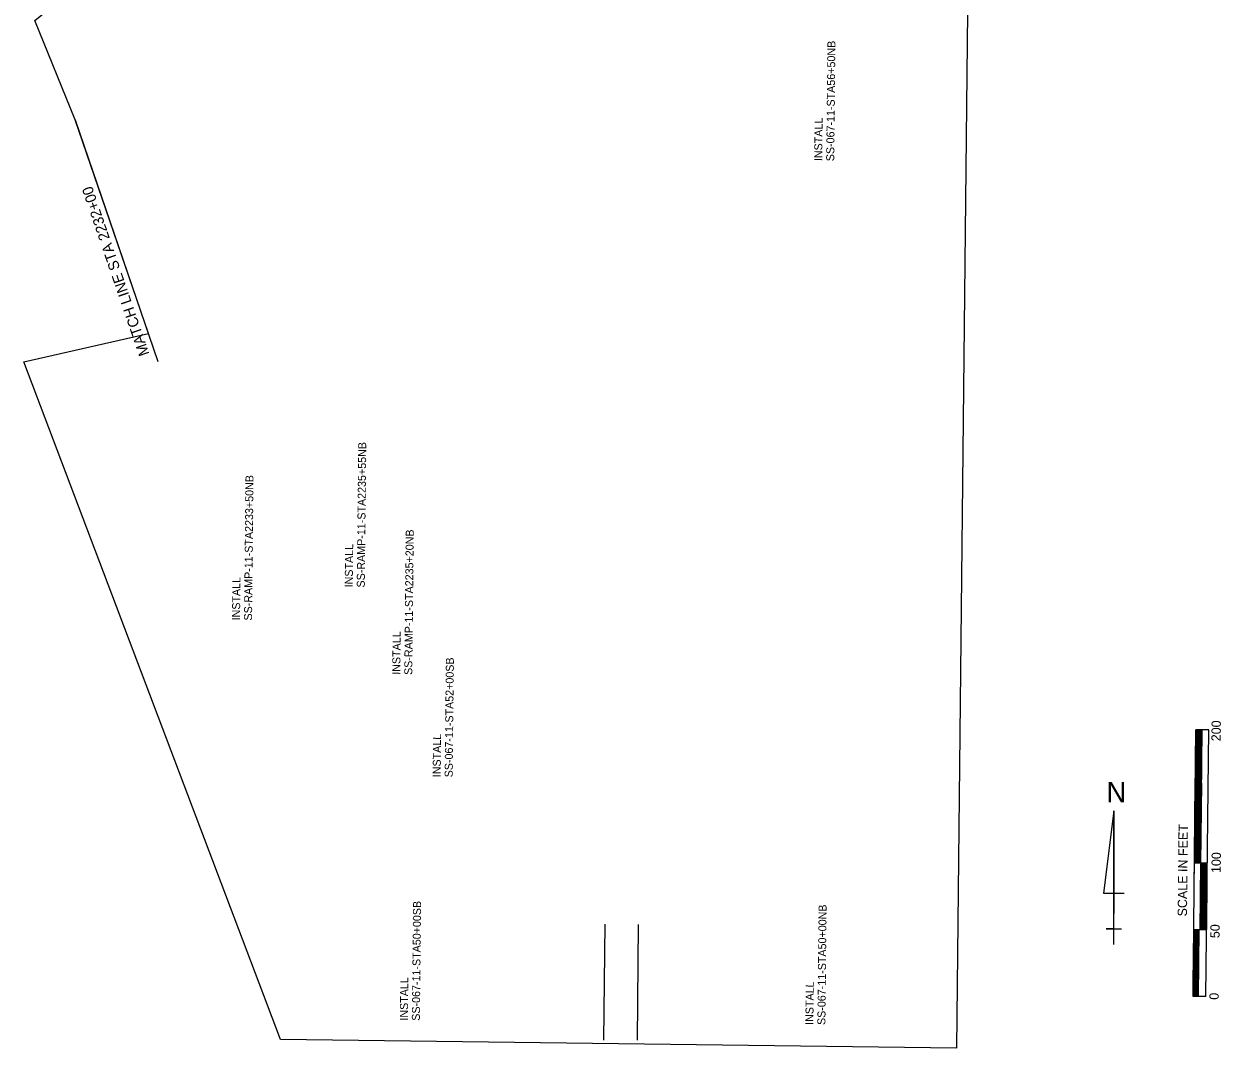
# Model space of a CAD drawing. Extents: x 1727808 to 1728800, y 771204 to 773048.
# Drawn here: x 1727861 to 1728759, y 771204 to 771972 of the extents above; entities that cross this region are included whole.
import ezdxf

# ---------------------------------------------------------------- set-up
doc = ezdxf.new("R2010")
doc.units = 0
for name, color, linetype in [('R_6IN_DBL_YELLOW_THERMOPLASTIC', 7, 'Continuous'), ('R_8IN_SOLID_WHITE_THERMO', 7, 'Continuous'), ('R_8IN_SOLID_YELLOW_THERMO', 7, 'Continuous'), ('R_PM_DOTTED_LINE', 7, 'Continuous'), ('R_RPM_TYPE 2_RED-WHITE', 7, 'Continuous'), ('R_WORDS_WHITE_THERMO', 7, 'Continuous')]:
    doc.layers.add(name, color=color, linetype=linetype)

msp = doc.modelspace()

# ---------------------------------------------------------------- linework, layer by layer
at = {"layer": 'R_6IN_DBL_YELLOW_THERMOPLASTIC'}
for p, q in [((1728296.7, 771296.95), (1728295.79, 771209.93)), ((1728321.73, 771296.68), (1728320.82, 771209.89))]:
    msp.add_line(p, q, dxfattribs=at)
at = {"layer": 'R_8IN_SOLID_WHITE_THERMO'}
msp.add_line((1727899.69, 771899.83), (1727961.67, 771718.73), dxfattribs=at)
at = {"layer": 'R_8IN_SOLID_YELLOW_THERMO'}
for p, q in [((1728738.52, 771322.68), (1728739.78, 771442.68)), ((1728739.53, 771342.68), (1728740.58, 771442.67)), ((1728749.4, 771442.58), (1728739.8, 771442.68)), ((1728740.33, 771342.67), (1728741.38, 771442.66)), ((1728741.13, 771342.66), (1728742.18, 771442.65)), ((1728741.93, 771342.65), (1728742.98, 771442.64)), ((1728742.73, 771342.64), (1728743.78, 771442.64)), ((1728743.53, 771342.63), (1728744.58, 771442.63)), ((1728747.29, 771242.59), (1728749.38, 771442.58)), ((1728737.69, 771242.69), (1728739.36, 771402.68)), ((1728743.53, 771342.63), (1728744.16, 771402.63)), ((1728748.34, 771342.58), (1728738.74, 771342.68)), ((1728743.01, 771292.64), (1728743.54, 771342.63)), ((1728743.81, 771292.63), (1728744.33, 771342.62)), ((1728744.61, 771292.62), (1728745.13, 771342.62)), ((1728745.41, 771292.61), (1728745.93, 771342.61)), ((1728746.21, 771292.6), (1728746.73, 771342.6)), ((1728747.01, 771292.59), (1728747.53, 771342.59)), ((1728747.7, 771282.58), (1728748.13, 771322.58)), ((1728747.81, 771292.58), (1728738.22, 771292.69)), ((1728738.49, 771242.68), (1728739.01, 771292.68)), ((1728739.28, 771242.67), (1728739.81, 771292.67)), ((1728740.09, 771242.66), (1728740.61, 771292.66)), ((1728740.89, 771242.65), (1728741.41, 771292.65)), ((1728741.69, 771242.65), (1728742.21, 771292.64)), ((1728737.69, 771242.69), (1728738.1, 771282.68)), ((1728747.29, 771242.59), (1728737.69, 771242.69))]:
    msp.add_line(p, q, dxfattribs=at)
at = {"layer": 'R_PM_DOTTED_LINE'}
for p, q in [((1728678.34, 771381.78), (1728670.64, 771320.24)), ((1728678.34, 771281.78), (1728678.34, 771381.78)), ((1728678.34, 771381.78), (1728678.34, 771304.85)), ((1728670.64, 771320.24), (1728686.03, 771320.24)), ((1728678.34, 771281.78), (1728678.34, 771304.85)), ((1728678.34, 771293.31), (1728672.57, 771293.31)), ((1728672.57, 771293.31), (1728684.1, 771293.31)), ((1728678.34, 771281.78), (1728678.34, 771293.31))]:
    msp.add_line(p, q, dxfattribs=at)
at = {"layer": 'R_RPM_TYPE 2_RED-WHITE'}
msp.add_lwpolyline([(1728560.41, 771204.04), (1728053.5, 771210.35), (1727861.19, 771718.38), (1727954.51, 771739.64), (1727899.69, 771899.83), (1727869.48, 771974.36), (1728062.71, 772130.76), (1727926.95, 772277.62), (1728224.75, 772757.78), (1728424.74, 772755.68), (1728523.33, 772753), (1728576.19, 772710.62)], close=True, dxfattribs=at)

# ---------------------------------------------------------------- texts
at = {"layer": 'R_8IN_SOLID_WHITE_THERMO'}
msp.add_text('MATCH LINE STA 2232+00', height=8, rotation=108.8916, dxfattribs=at).set_placement((1727955.34, 771724.35))
at = {"layer": 'R_8IN_SOLID_YELLOW_THERMO'}
for s, height, p in [('200', 7.001, (1728758.38, 771433.96)), ('SCALE IN FEET', 7.0007, (1728733.08, 771302.67)), ('100', 7.001, (1728758.4, 771335.2)), ('50', 7.001, (1728757.54, 771286.39)), ('0', 7, (1728756.87, 771240.21))]:
    msp.add_text(s, height=height, rotation=89.40027, dxfattribs=at).set_placement(p)
at = {"layer": 'R_PM_DOTTED_LINE'}
msp.add_text('N', height=15.38, rotation=360, dxfattribs=at).set_placement((1728672.7, 771388.19))
at = {"layer": 'R_WORDS_WHITE_THERMO'}
for s, p in [('SS-067-11-STA56+50NB', (1728468.61, 771868.72)), ('INSTALL', (1728459.61, 771868.81)), ('SS-RAMP-11-STA2235+55NB', (1728116.69, 771549.22)), ('SS-RAMP-11-STA2233+50NB', (1728032.17, 771524.46)), ('SS-RAMP-11-STA2235+20NB', (1728152.3, 771483.69)), ('INSTALL', (1728107.69, 771549.32)), ('INSTALL', (1728023.17, 771524.56)), ('INSTALL', (1728143.3, 771483.79)), ('SS-067-11-STA52+00SB', (1728182.58, 771406.93)), ('INSTALL', (1728173.58, 771407.03)), ('SS-067-11-STA50+00SB', (1728158, 771224.47)), ('SS-067-11-STA50+00NB', (1728462.01, 771221.29)), ('INSTALL', (1728149, 771224.57)), ('INSTALL', (1728453.01, 771221.39))]:
    msp.add_text(s, height=6, rotation=89.4, dxfattribs=at).set_placement(p)

doc.saveas('drawing.dxf')
